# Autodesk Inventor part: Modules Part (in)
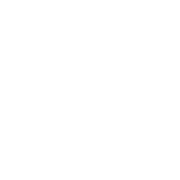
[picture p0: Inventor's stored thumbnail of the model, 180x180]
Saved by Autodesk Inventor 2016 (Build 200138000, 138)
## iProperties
Created: 2014-08
Part Number: Modules Part (in)
Material: Generic
Document SubType Name: Modeling
Designer: Wally
Manufacturer: Standard
Standards Organization: Custom
Density: 1 g/cm^3
Appearance: Default
Author: Wally
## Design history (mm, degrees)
node "Sketch1"
